// Mitsubishi GX Works2 project: MC-20MR-6MT-FE430A-FX-A(经济款)例程   PLC: FX1S

PROGRAM MAIN
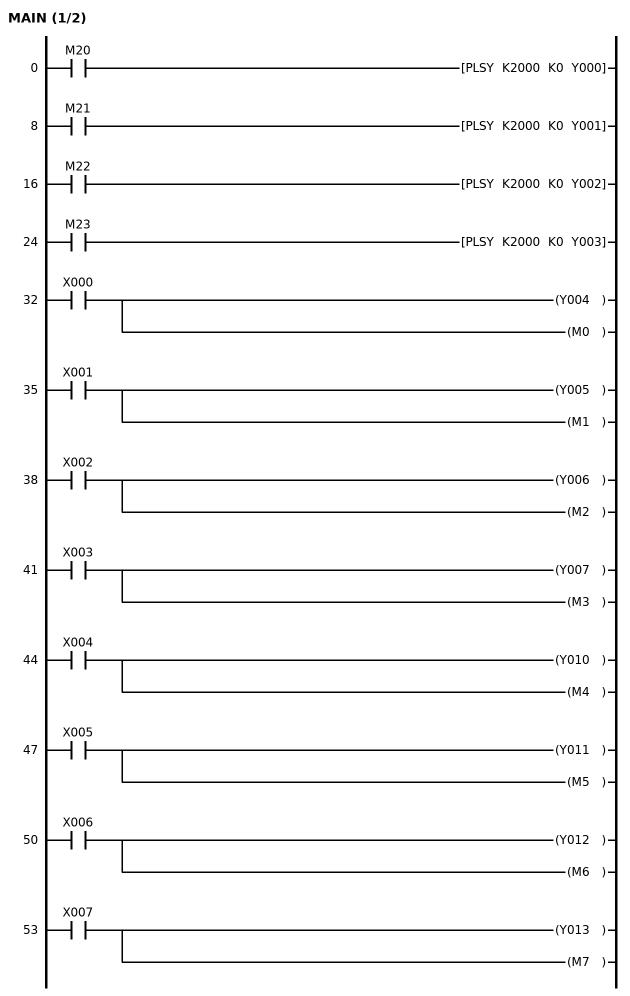
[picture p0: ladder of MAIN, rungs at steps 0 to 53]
0     LD      M20
      PLSY    K2000 K0 Y000
8     LD      M21
      PLSY    K2000 K0 Y001
16    LD      M22
      PLSY    K2000 K0 Y002
24    LD      M23
      PLSY    K2000 K0 Y003
32    LD      X000
      OUT     Y004
      OUT     M0
35    LD      X001
      OUT     Y005
      OUT     M1
38    LD      X002
      OUT     Y006
      OUT     M2
41    LD      X003
      OUT     Y007
      OUT     M3
44    LD      X004
      OUT     Y010
      OUT     M4
47    LD      X005
      OUT     Y011
      OUT     M5
50    LD      X006
      OUT     Y012
      OUT     M6
53    LD      X007
      OUT     Y013
      OUT     M7
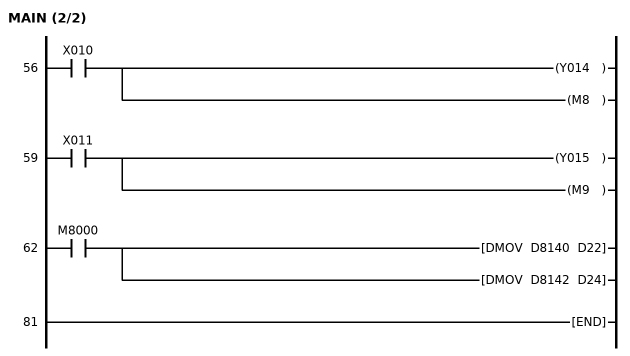
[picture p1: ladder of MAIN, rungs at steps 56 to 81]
56    LD      X010
      OUT     Y014
      OUT     M8
59    LD      X011
      OUT     Y015
      OUT     M9
62    LD      M8000
      DMOV    D8140 D22
      DMOV    D8142 D24
81    END
END_PROGRAM
